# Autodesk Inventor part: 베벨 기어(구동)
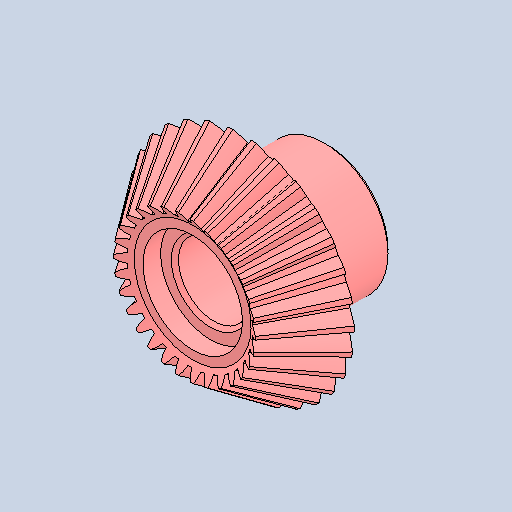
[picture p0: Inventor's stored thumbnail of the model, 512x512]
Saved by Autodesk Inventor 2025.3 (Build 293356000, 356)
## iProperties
Created: 2026-01
Part Number: 베벨 기어(구동)
Material: 강철, 합금
Document SubType Name: Modeling
Designer: pc6
Density: 7.73 g/cm^3
Appearance: 기본값
Author: jhkim
Sending System: Autodesk Inventor 2026
Preprocessor: ST-DEVELOPER v20.1
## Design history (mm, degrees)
feature "Solid1"
node "솔리드1"
